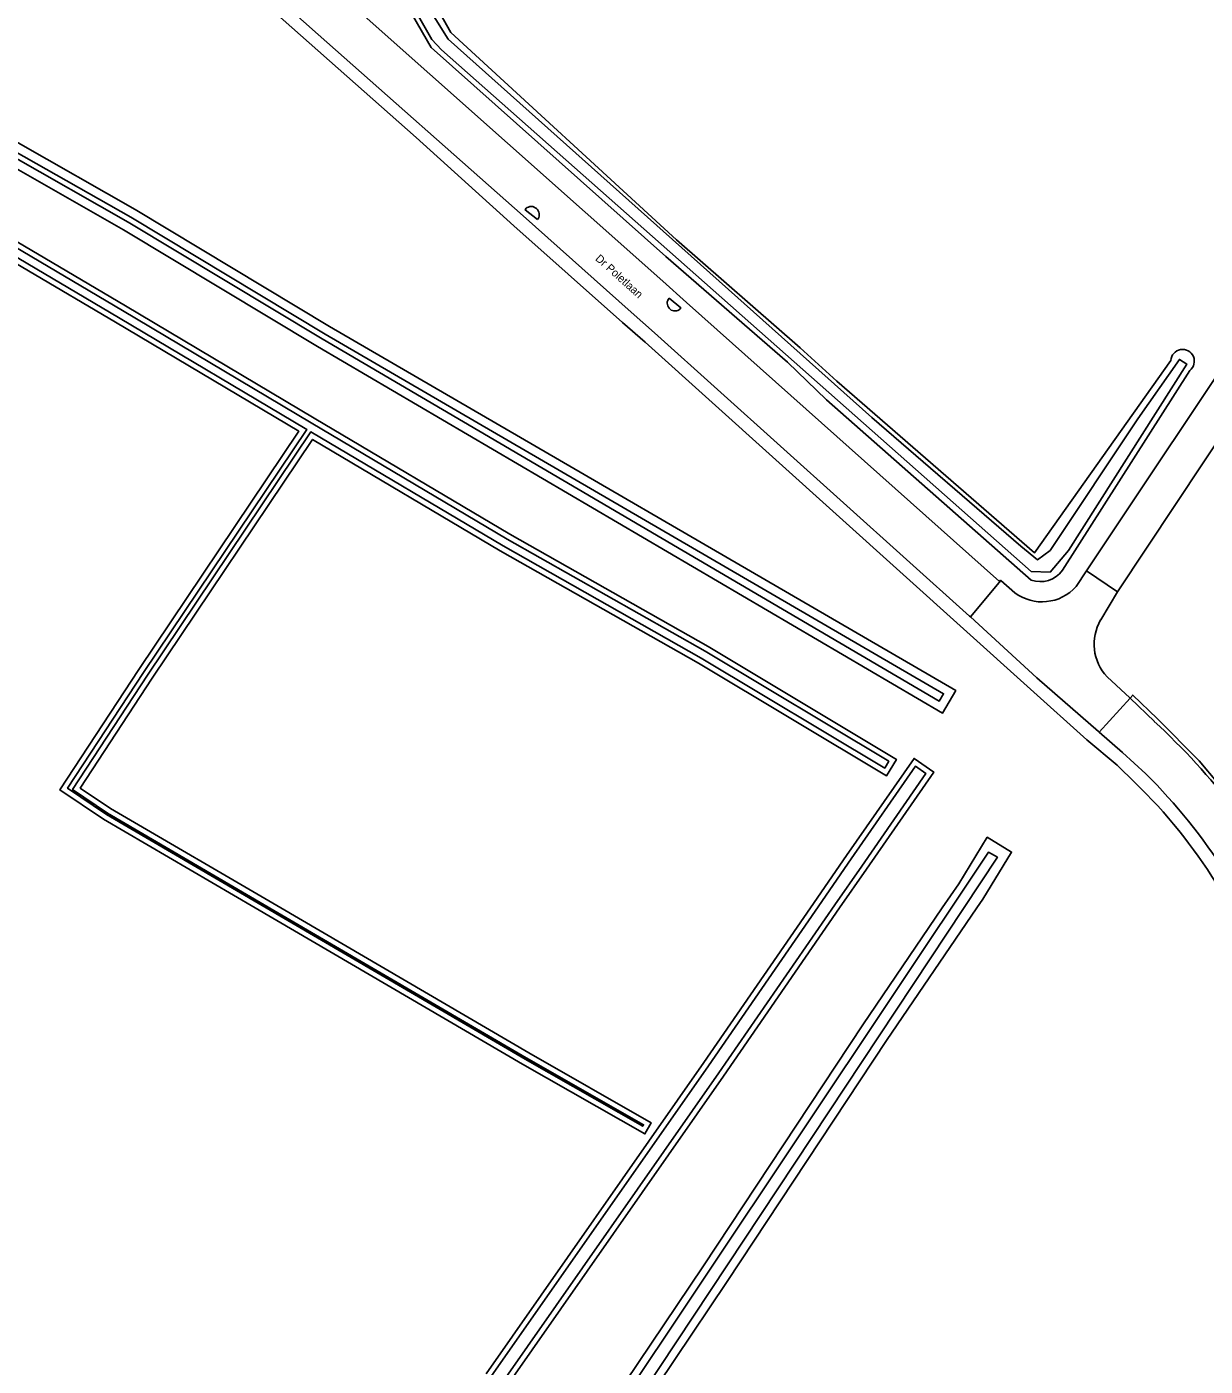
# Model space of a CAD drawing. Extents: x 158132 to 159664, y 385256 to 387218.
# Drawn here: x 159296.3 to 159443.6, y 385692.7 to 385860.1 of the extents above; entities that cross this region are included whole.
import ezdxf

# ---------------------------------------------------------------- set-up
doc = ezdxf.new("R2010")
doc.units = 0
for name, color, linetype in [('IMGEO_Berm_groen', 7, 'Continuous'), ('IMGEO_Fietspad_open', 7, 'Continuous'), ('IMGEO_Gemengd_bos', 7, 'Continuous'), ('IMGEO_Loofbos', 7, 'Continuous'), ('IMGEO_Oever', 7, 'Continuous'), ('IMGEO_Openbare_ruimte_label', 7, 'Continuous'), ('IMGEO_Rijbaan_lokaal_gesloten', 7, 'Continuous'), ('IMGEO_Rijbaan_lokaal_open', 7, 'Continuous'), ('IMGEO_Verkeerseiland_gesloten', 7, 'Continuous'), ('IMGEO_Waterloop', 7, 'Continuous')]:
    doc.layers.add(name, color=color, linetype=linetype)

msp = doc.modelspace()

# ---------------------------------------------------------------- linework, layer by layer
at = {"layer": 'IMGEO_Berm_groen'}
for points in [[(159434.55, 385776.59), (159434.2, 385776.23), (159437.24, 385773.29)], [(159447.61, 385762.72), (159442.83, 385768.4), (159437.58, 385773.66), (159434.55, 385776.59)]]:
    msp.add_lwpolyline(points, dxfattribs=at)
msp.add_arc((159378.59, 385709.49), 86.66, 27.8686, 47.4123, dxfattribs=at)
at = {"layer": 'IMGEO_Fietspad_open'}
for points in [[(159358.33, 385836.48), (159332.7, 385859.13), (159312.23, 385877.33), (159299.53, 385888.62), (159298.65, 385887.27), (159299.79, 385886.27), (159344.98, 385846.27), (159357.19, 385835.22), (159370.76, 385823.15), (159373.58, 385820.69), (159421.75, 385777.33), (159428.81, 385771), (159432.59, 385767.85), (159434.84, 385765.65)], [(159436.18, 385766.75), (159433.27, 385769.44), (159430.35, 385771.96), (159430.24, 385772.05), (159422.54, 385778.77), (159414.24, 385786.36), (159414.14, 385786.45), (159374.77, 385821.88), (159371.86, 385824.45), (159358.33, 385836.48)]]:
    msp.add_lwpolyline(points, dxfattribs=at)
for centre, radius, start, end in [((159385.95, 385716.04), 71.37, 32.4563, 45.2722), ((159388.26, 385717.77), 66.8, 31.9147, 45.7833)]:
    msp.add_arc(centre, radius, start, end, dxfattribs=at)
at = {"layer": 'IMGEO_Gemengd_bos'}
for points in [[(159434.84, 385765.65), (159432.59, 385767.85), (159428.81, 385771), (159421.75, 385777.33), (159373.58, 385820.69), (159370.76, 385823.15), (159357.19, 385835.22), (159344.98, 385846.27), (159299.79, 385886.27), (159298.65, 385887.27), (159299.53, 385888.62), (159293.41, 385894.06), (159291.93, 385891.84), (159291.02, 385890.47), (159271.81, 385861.09), (159269.62, 385857.79), (159229.84, 385797.99), (159195.96, 385750), (159189.87, 385741.38), (159170.62, 385712.2), (159153.34, 385687.5)], [(159286.8, 385838.12), (159308.61, 385825.24), (159332.2, 385811.21), (159356.68, 385796.7), (159381.45, 385782.68), (159405, 385768.56), (159403.77, 385766.51), (159380.24, 385780.6), (159355.48, 385794.62), (159332.01, 385808.54), (159311.98, 385778.7), (159302.97, 385764.97), (159306.74, 385762.43), (159328.03, 385750), (159359.06, 385731.88), (159374.34, 385723.16), (159373.55, 385721.77), (159358.26, 385730.49), (159324.86, 385750), (159305.89, 385761.08), (159300.44, 385764.75), (159310.31, 385779.8), (159330.28, 385809.56), (159307.38, 385823.18), (159285.6, 385836.04)], [(159380.91, 385730.69), (159394.25, 385750), (159398.77, 385756.54), (159407.2, 385768.68), (159409.66, 385766.97), (159401.24, 385754.83), (159397.9, 385750), (159383.38, 385728.98), (159356.19, 385690.09)], [(159380.9, 385705.28), (159400.79, 385735.41), (159410.72, 385750), (159412.79, 385753.03), (159416.36, 385758.84), (159419.39, 385756.98), (159415.78, 385751.1), (159415.03, 385750), (159403.74, 385733.43), (159383.86, 385703.31), (159364.2, 385674.09), (159352.18, 385655.54), (159338.58, 385635.74), (159331.28, 385624.58)], [(159353.73, 385691.8), (159380.91, 385730.69)], [(159323.01, 385611.87), (159314.43, 385599.45), (159294.2, 385569.2), (159287.02, 385558.66), (159276.56, 385542.23), (159263.64, 385523.9), (159249.27, 385501.89), (159248.02, 385500), (159216.69, 385452.66), (159213.72, 385454.62), (159243.75, 385500), (159246.3, 385503.85), (159260.69, 385525.9), (159273.61, 385544.22), (159284.05, 385560.61), (159291.25, 385571.2), (159311.46, 385601.42), (159335.63, 385637.74), (159349.21, 385657.51), (159361.23, 385676.05), (159380.9, 385705.28)]]:
    msp.add_lwpolyline(points, dxfattribs=at)
msp.add_lwpolyline([(159273.36, 385854.53), (159274.78, 385857.06), (159295.23, 385845.59), (159309.84, 385837.27), (159334.13, 385822.64), (159412.41, 385777.16), (159410.74, 385774.32), (159332.64, 385820.16), (159308.4, 385834.75), (159293.81, 385843.06)], close=True, dxfattribs=at)
msp.add_arc((159388.26, 385717.77), 66.8, 31.9147, 45.7833, dxfattribs=at)
at = {"layer": 'IMGEO_Loofbos'}
for points in [[(159422.73, 386058.55), (159423.83, 386057.81), (159382.67, 385996.63), (159381.32, 385997.52), (159381.21, 385997.35), (159381.17, 385997.29), (159380.03, 385995.6), (159369.94, 385980.63), (159369.74, 385980.34), (159370.97, 385979.48), (159366.24, 385972.46), (159338.24, 385931.62), (159323.76, 385909.93), (159322.34, 385907.8), (159320.63, 385878.88), (159321.2, 385876.76), (159336.97, 385862.82), (159375.8, 385828.33), (159378.77, 385825.67), (159417.87, 385790.77), (159418.01, 385790.94), (159418.04, 385790.91), (159419.79, 385789.39)], [(159506.91, 385901.32), (159506.1, 385900.24), (159500, 385890.93), (159491.83, 385878.48), (159475.4, 385853.85), (159472.26, 385849.15), (159432.64, 385789.49), (159430.53, 385785.98)], [(159427.46, 385790.16), (159428.76, 385792.11), (159471.78, 385856.54), (159487.71, 385880.54), (159500, 385899.39), (159500.64, 385900.37)], [(159334.32, 385885.93), (159349.29, 385859.41), (159377.52, 385833.49)], [(159421.84, 385790.96), (159396.24, 385813.5), (159391.38, 385818.18), (159376.18, 385831.42), (159346.82, 385857.51), (159332.05, 385883.18)], [(159377.52, 385833.49), (159392.98, 385819.98), (159397.53, 385815.84), (159422.24, 385794.37), (159439.3, 385818.41)], [(159441.66, 385817.15), (159425.76, 385792.19)], [(159431.33, 385778.87), (159434.16, 385776.27), (159434.2, 385776.23), (159434.55, 385776.59), (159437.58, 385773.66), (159442.83, 385768.4), (159447.61, 385762.72)]]:
    msp.add_lwpolyline(points, dxfattribs=at)
for centre, radius, start, end in [((159440.77, 385818.32), 1.47, 307.2302, 176.4963), ((159422.98, 385794.21), 3.44, 250.7531, 324.0265), ((159423.2, 385793.94), 5.69, 233.0715, 318.4251), ((159435.71, 385782.97), 6, 149.8126, 223.1116)]:
    msp.add_arc(centre, radius, start, end, dxfattribs=at)
at = {"layer": 'IMGEO_Oever'}
for points in [[(159362.22, 385960.32), (159373.21, 385976.23), (159382.77, 385990.18), (159382.93, 385991.72), (159382.52, 385992.13), (159381.94, 385992.69), (159380.53, 385992.28), (159373.82, 385982.57), (159363.26, 385967.23), (159348.34, 385945.7), (159344.46, 385939.76), (159336.73, 385927.18), (159332.47, 385917.55), (159330.03, 385906.73), (159329.54, 385896.14), (159329.82, 385892.62), (159330.37, 385888.12), (159332.05, 385883.18), (159346.82, 385857.51), (159376.18, 385831.42), (159391.38, 385818.18), (159396.24, 385813.5), (159421.84, 385790.96)], [(159439.3, 385818.41), (159422.24, 385794.37), (159397.53, 385815.84), (159392.98, 385819.98), (159377.52, 385833.49), (159349.29, 385859.41), (159334.32, 385885.93), (159332.78, 385893.49), (159332.66, 385896.81), (159332.73, 385906.12), (159334.9, 385916.12), (159338.84, 385924.72), (159347.15, 385937.71), (159352.38, 385945.57), (159362.22, 385960.32)], [(159344.54, 385865.62), (159348.96, 385858.57), (159401.91, 385811.27), (159420.54, 385795.2), (159422.65, 385793.51), (159424.21, 385794.66), (159435.19, 385811.1), (159440.37, 385818.55), (159441.29, 385817.95), (159426.51, 385794.68), (159424.21, 385791.97), (159421.84, 385792.05), (159348.12, 385857.23), (159346.93, 385858.51), (159333.43, 385882.16)], [(159285.6, 385836.04), (159307.38, 385823.18), (159330.28, 385809.56), (159310.31, 385779.8), (159300.44, 385764.75), (159305.89, 385761.08), (159324.86, 385750), (159358.26, 385730.49), (159373.55, 385721.77), (159374.34, 385723.16), (159359.06, 385731.88), (159328.03, 385750), (159306.74, 385762.43), (159302.97, 385764.97), (159311.98, 385778.7), (159332.01, 385808.54), (159355.48, 385794.62), (159380.24, 385780.6), (159403.77, 385766.51), (159405, 385768.56), (159381.45, 385782.68), (159356.68, 385796.7), (159332.2, 385811.21), (159308.61, 385825.24), (159286.8, 385838.12)], [(159286.45, 385837.51), (159308.25, 385824.64), (159331.84, 385810.61), (159356.33, 385796.09), (159381.1, 385782.07), (159404.04, 385768.32), (159403.53, 385767.47), (159380.6, 385781.21), (159355.83, 385795.23), (159331.79, 385809.48), (159311.39, 385779.09), (159302.01, 385764.78), (159306.37, 385761.84), (159327.68, 385749.4), (159358.71, 385731.27), (159373.39, 385722.9), (159373.29, 385722.72), (159358.61, 385731.1), (159325.21, 385750.6), (159306.26, 385761.67), (159301.4, 385764.95), (159310.89, 385779.42), (159331.28, 385809.79), (159307.74, 385823.78), (159285.95, 385836.65)], [(159425.76, 385792.19), (159441.66, 385817.15)], [(159356.19, 385690.09), (159383.38, 385728.98), (159397.9, 385750), (159401.24, 385754.83), (159409.66, 385766.97), (159407.2, 385768.68), (159398.77, 385756.54), (159394.25, 385750), (159380.91, 385730.69), (159353.73, 385691.8)], [(159354.3, 385691.4), (159381.49, 385730.29), (159394.83, 385749.6), (159399.35, 385756.14), (159407.38, 385767.71), (159408.69, 385766.79), (159400.66, 385755.23), (159397.32, 385750.4), (159382.8, 385729.38), (159355.61, 385690.49)], [(159364.2, 385674.09), (159383.86, 385703.31), (159403.74, 385733.43), (159415.03, 385750), (159415.78, 385751.1), (159419.39, 385756.98), (159416.36, 385758.84), (159412.79, 385753.03), (159410.72, 385750), (159400.79, 385735.41), (159380.9, 385705.28), (159361.23, 385676.05)], [(159357.31, 385668.29), (159416.5, 385756.96), (159417.63, 385756.34), (159331.07, 385625.71)]]:
    msp.add_lwpolyline(points, dxfattribs=at)
for points in [[(159334.13, 385822.64), (159309.84, 385837.27), (159295.23, 385845.59), (159274.78, 385857.06), (159273.36, 385854.53), (159293.81, 385843.06), (159308.4, 385834.75), (159332.64, 385820.16), (159410.74, 385774.32), (159412.41, 385777.16)], [(159274.87, 385854.95), (159275.2, 385855.54), (159294.68, 385844.62), (159309.28, 385836.31), (159333.57, 385821.68), (159410.89, 385776.76), (159410.34, 385775.83), (159333.21, 385821.11), (159308.96, 385835.71), (159294.35, 385844.03)]]:
    msp.add_lwpolyline(points, close=True, dxfattribs=at)
for centre, radius, start, end in [((159440.77, 385818.32), 1.47, 307.2302, 176.4963), ((159422.98, 385794.21), 3.44, 250.7531, 324.0265)]:
    msp.add_arc(centre, radius, start, end, dxfattribs=at)
at = {"layer": 'IMGEO_Rijbaan_lokaal_gesloten'}
for points in [[(159512.21, 385906.44), (159510.14, 385907.83), (159509.73, 385908.11), (159509.1, 385908.53), (159507.06, 385908.68), (159506.68, 385908.42), (159505.13, 385907.26), (159500.64, 385900.37), (159500, 385899.39), (159487.71, 385880.54), (159471.78, 385856.54), (159428.76, 385792.11), (159432.64, 385789.49), (159472.26, 385849.15), (159475.4, 385853.85), (159491.83, 385878.48), (159500, 385890.93), (159506.1, 385900.24), (159506.91, 385901.32)], [(159437.24, 385773.29), (159434.2, 385776.23), (159430.35, 385771.96), (159433.27, 385769.44), (159436.18, 385766.75)]]:
    msp.add_lwpolyline(points, dxfattribs=at)
for points in [[(159336.97, 385862.82), (159321.2, 385876.76), (159319.11, 385878.6), (159315.86, 385881.48), (159312.23, 385877.33), (159332.7, 385859.13), (159358.33, 385836.48), (159371.86, 385824.45), (159374.77, 385821.88), (159414.14, 385786.45), (159414.24, 385786.36), (159418.04, 385790.91), (159418.01, 385790.94), (159417.87, 385790.77), (159378.77, 385825.67), (159375.8, 385828.33)], [(159360.12, 385836.02), (159358.61, 385837.23), (159358.72, 385837.43), (159358.83, 385837.51), (159359, 385837.58), (159359.18, 385837.63), (159359.35, 385837.64), (159359.53, 385837.63), (159359.7, 385837.58), (159359.86, 385837.5), (159360.01, 385837.4), (159360.14, 385837.27), (159360.23, 385837.12), (159360.31, 385836.96), (159360.35, 385836.78), (159360.36, 385836.6), (159360.34, 385836.43), (159360.3, 385836.29), (159360.27, 385836.21)], [(159376.59, 385826.2), (159378.06, 385824.98), (159377.93, 385824.81), (159377.83, 385824.74), (159377.68, 385824.66), (159377.51, 385824.61), (159377.34, 385824.59), (159377.17, 385824.6), (159377.01, 385824.65), (159376.85, 385824.71), (159376.71, 385824.81), (159376.58, 385824.93), (159376.49, 385825.07), (159376.41, 385825.22), (159376.37, 385825.39), (159376.35, 385825.56), (159376.36, 385825.73), (159376.41, 385825.89), (159376.46, 385826.01)]]:
    msp.add_lwpolyline(points, close=True, dxfattribs=at)
for centre, radius, start, end in [((159378.59, 385709.49), 86.66, 27.8686, 47.4123), ((159385.95, 385716.04), 71.37, 32.4563, 45.2722)]:
    msp.add_arc(centre, radius, start, end, dxfattribs=at)
at = {"layer": 'IMGEO_Rijbaan_lokaal_open'}
for points in [[(159430.53, 385785.98), (159432.64, 385789.49), (159428.76, 385792.11), (159427.46, 385790.16)], [(159419.79, 385789.39), (159418.04, 385790.91), (159414.24, 385786.36), (159422.54, 385778.77), (159430.24, 385772.05), (159430.35, 385771.96), (159434.2, 385776.23), (159434.16, 385776.27), (159431.33, 385778.87)]]:
    msp.add_lwpolyline(points, dxfattribs=at)
for centre, radius, start, end in [((159423.2, 385793.94), 5.69, 233.0715, 318.4251), ((159435.71, 385782.97), 6, 149.8126, 223.1116)]:
    msp.add_arc(centre, radius, start, end, dxfattribs=at)
at = {"layer": 'IMGEO_Verkeerseiland_gesloten'}
for points in [[(159360.12, 385836.02), (159360.27, 385836.21), (159360.3, 385836.29), (159360.34, 385836.43), (159360.36, 385836.6), (159360.35, 385836.78), (159360.31, 385836.96), (159360.23, 385837.12), (159360.14, 385837.27), (159360.01, 385837.4), (159359.86, 385837.5), (159359.7, 385837.58), (159359.53, 385837.63), (159359.35, 385837.64), (159359.18, 385837.63), (159359, 385837.58), (159358.83, 385837.51), (159358.72, 385837.43), (159358.61, 385837.23)], [(159376.59, 385826.2), (159376.46, 385826.01), (159376.41, 385825.89), (159376.36, 385825.73), (159376.35, 385825.56), (159376.37, 385825.39), (159376.41, 385825.22), (159376.49, 385825.07), (159376.58, 385824.93), (159376.71, 385824.81), (159376.85, 385824.71), (159377.01, 385824.65), (159377.17, 385824.6), (159377.34, 385824.59), (159377.51, 385824.61), (159377.68, 385824.66), (159377.83, 385824.74), (159377.93, 385824.81), (159378.06, 385824.98)]]:
    msp.add_lwpolyline(points, close=True, dxfattribs=at)
at = {"layer": 'IMGEO_Waterloop'}
for points in [[(159333.43, 385882.16), (159346.93, 385858.51), (159348.12, 385857.23), (159421.84, 385792.05), (159424.21, 385791.97), (159426.51, 385794.68), (159441.29, 385817.95), (159440.37, 385818.55), (159435.19, 385811.1), (159424.21, 385794.66), (159422.65, 385793.51), (159420.54, 385795.2), (159401.91, 385811.27), (159348.96, 385858.57), (159344.54, 385865.62)], [(159285.95, 385836.65), (159307.74, 385823.78), (159331.28, 385809.79), (159310.89, 385779.42), (159301.4, 385764.95), (159306.26, 385761.67), (159325.21, 385750.6), (159358.61, 385731.1), (159373.29, 385722.72), (159373.39, 385722.9), (159358.71, 385731.27), (159327.68, 385749.4), (159306.37, 385761.84), (159302.01, 385764.78), (159311.39, 385779.09), (159331.79, 385809.48), (159355.83, 385795.23), (159380.6, 385781.21), (159403.53, 385767.47), (159404.04, 385768.32), (159381.1, 385782.07), (159356.33, 385796.09), (159331.84, 385810.61), (159308.25, 385824.64), (159286.45, 385837.51)], [(159355.61, 385690.49), (159382.8, 385729.38), (159397.32, 385750.4), (159400.66, 385755.23), (159408.69, 385766.79), (159407.38, 385767.71), (159399.35, 385756.14), (159394.83, 385749.6), (159381.49, 385730.29), (159354.3, 385691.4)], [(159331.07, 385625.71), (159417.63, 385756.34), (159416.5, 385756.96), (159357.31, 385668.29)]]:
    msp.add_lwpolyline(points, dxfattribs=at)
msp.add_lwpolyline([(159274.87, 385854.95), (159294.35, 385844.03), (159308.96, 385835.71), (159333.21, 385821.11), (159410.34, 385775.83), (159410.89, 385776.76), (159333.57, 385821.68), (159309.28, 385836.31), (159294.68, 385844.62), (159275.2, 385855.54)], close=True, dxfattribs=at)

# ---------------------------------------------------------------- texts
at = {"layer": 'IMGEO_Openbare_ruimte_label'}
msp.add_text('Dr Poletlaan', height=1, rotation=318.1619, dxfattribs=at).set_placement((159367.28, 385831.02))

doc.saveas('drawing.dxf')
